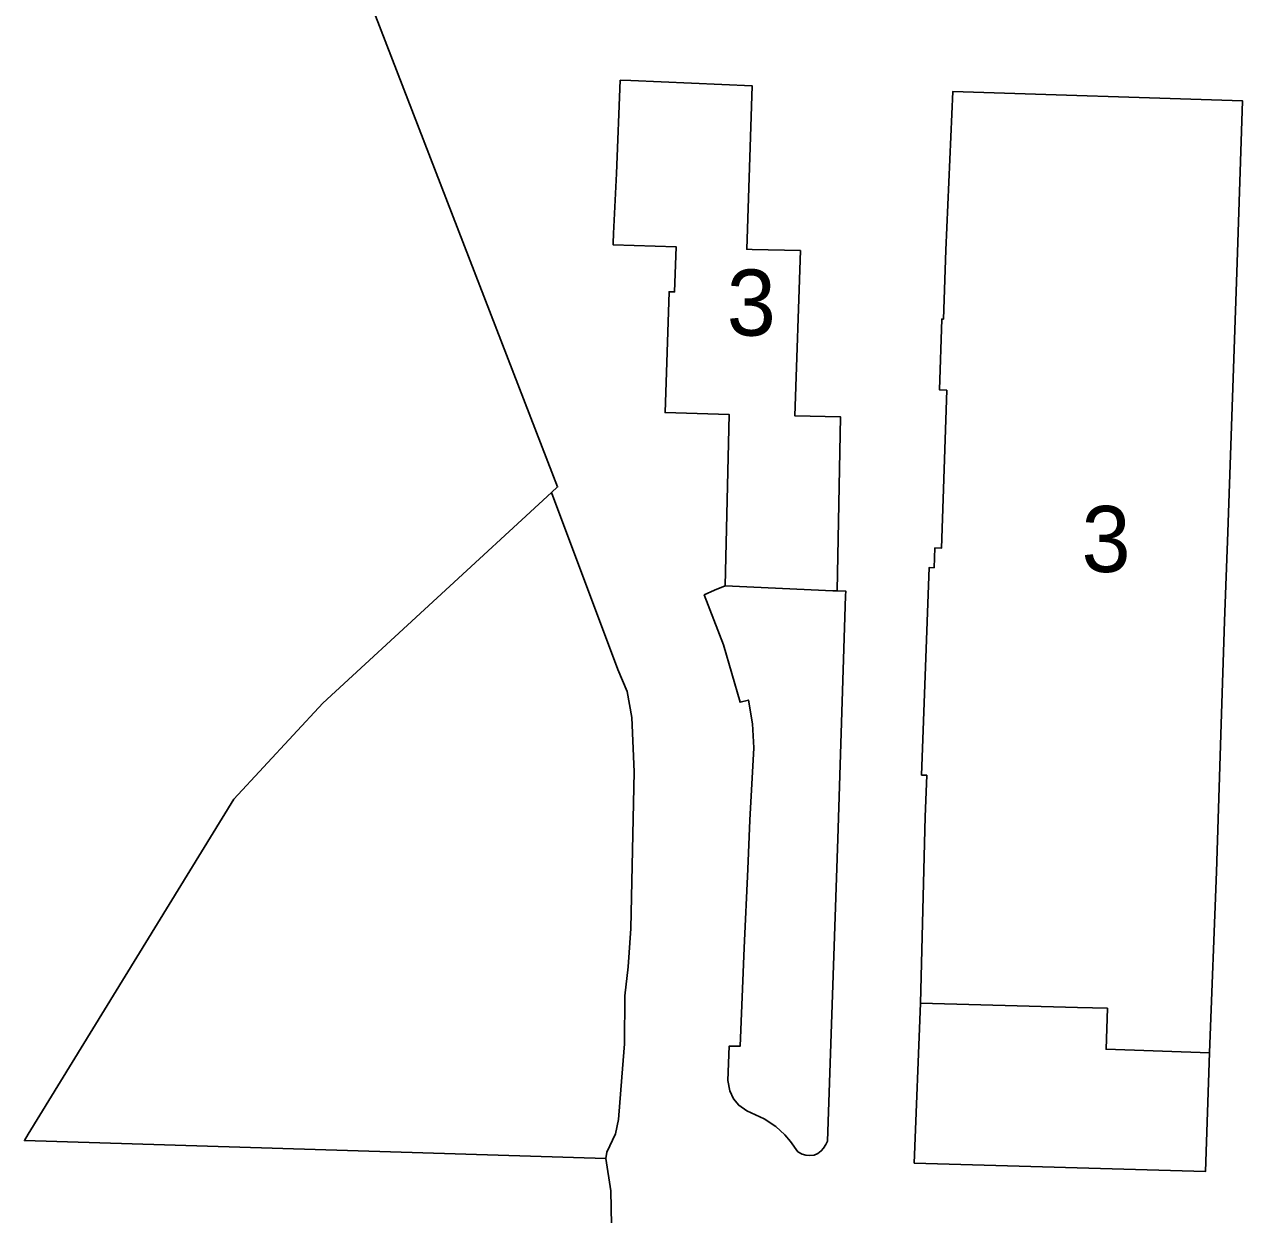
# Model space of a CAD drawing. Extents: x 598968 to 613553, y 4409678 to 4430833.
# Drawn here: x 607300.1 to 607521.4, y 4415642.7 to 4415858.9 of the extents above; entities that cross this region are included whole.
import ezdxf

# ---------------------------------------------------------------- set-up
doc = ezdxf.new("R2010")
doc.units = 0
doc.layers.add('1', color=7, linetype='Continuous')
doc.layers.add("ZONA 3. ILLES  D'EDIFICIS ENTRE MITGERES. EIXAMPLE.", color=7, linetype='Continuous')

msp = doc.modelspace()

# ---------------------------------------------------------------- linework, layer by layer
at = {"layer": '1'}
for points in [[(607406.8143, 4415637.7598), (607406.6242, 4415647.0096), (607405.7007, 4415652.8821), (607300.0976, 4415656.139), (607300.8174, 4415657.3116), (607338.1666, 4415718.1558), (607354.297, 4415735.5965), (607395.8401, 4415773.8555), (607396.9598, 4415774.8866), (607328.465, 4415952.2302)], [(607328.465, 4415952.2302), (607396.9598, 4415774.8866), (607395.8401, 4415773.8555), (607407.8823, 4415741.7238), (607409.6023, 4415737.7039), (607410.4424, 4415733.004), (607410.9024, 4415723.1242), (607410.2425, 4415694.6645), (607409.8025, 4415687.6845), (607409.2025, 4415682.4346), (607409.1176, 4415673.7297), (607408.6326, 4415667.6848), (607408.0326, 4415659.9648), (607407.4927, 4415657.3648), (607405.9392, 4415654.0676), (607405.7007, 4415652.8821), (607406.6242, 4415647.0096), (607406.8143, 4415637.7598)]]:
    msp.add_lwpolyline(points, dxfattribs=at)
for points in [[(607447.7421, 4415755.99), (607449.3024, 4415755.9611), (607449.2618, 4415755.0744), (607447.8579, 4415710.9642), (607445.9849, 4415656.0099), (607445.7069, 4415655.4515), (607445.2822, 4415654.7456), (607444.8522, 4415654.2656), (607444.2208, 4415653.7724), (607443.5495, 4415653.5165), (607442.7978, 4415653.4221), (607442.0503, 4415653.4934), (607441.3723, 4415653.7055), (607440.6261, 4415654.1081), (607439.2823, 4415655.9954), (607438.2623, 4415657.2054), (607436.6323, 4415658.6954), (607434.5023, 4415660.1053), (607431.3374, 4415661.5652), (607429.8624, 4415662.5503), (607428.8924, 4415663.7452), (607428.2324, 4415665.1651), (607427.8724, 4415667.0651), (607428.1224, 4415673.275), (607430.1355, 4415673.3169), (607430.879, 4415691.1786), (607431.5207, 4415705.442), (607431.9172, 4415714.3246), (607432.6221, 4415727.4745), (607432.3521, 4415731.8504), (607431.6268, 4415736.1744), (607430.1121, 4415735.7844), (607427.0821, 4415746.1941), (607423.6121, 4415755.254), (607425.4621, 4415756.134), (607427.3921, 4415756.914), (607427.4073, 4415756.9133), (607428.103, 4415788.0669), (607416.4766, 4415788.3969), (607417.212, 4415810.3432), (607418.212, 4415810.3032), (607418.532, 4415818.4831), (607407.0421, 4415818.8829), (607407.0542, 4415819.1429), (607407.1221, 4415820.9029), (607407.642, 4415831.8128), (607408.342, 4415848.7526), (607410.2619, 4415848.7026), (607432.2817, 4415847.773), (607431.341, 4415818.0563), (607432.3018, 4415818.0234), (607441.0867, 4415817.8285), (607440.0918, 4415787.7839), (607448.3417, 4415787.624)], [(607520.4409, 4415815.675), (607518.7296, 4415766.6552), (607518.1311, 4415750.4957), (607517.5212, 4415731.796), (607516.6613, 4415704.9363), (607515.3915, 4415672.1366), (607515.3907, 4415672.1133), (607514.6715, 4415650.5469), (607461.7621, 4415652.0659), (607462.862, 4415681.1156), (607463.7319, 4415714.9752), (607464.0219, 4415722.4951), (607463.0819, 4415722.5351), (607464.4517, 4415760.2346), (607465.3686, 4415760.1957), (607465.5217, 4415763.7946), (607466.6805, 4415763.755), (607467.6617, 4415792.4592), (607466.3616, 4415792.4943), (607466.7515, 4415805.3842), (607467.0498, 4415805.3739), (607467.4815, 4415817.894), (607468.7914, 4415846.7437), (607521.4108, 4415845.0147)], [(607405.7007, 4415652.8821), (607405.9392, 4415654.0676), (607407.4927, 4415657.3648), (607408.0326, 4415659.9648), (607408.6326, 4415667.6848), (607409.1176, 4415673.7297), (607409.2025, 4415682.4346), (607409.8025, 4415687.6845), (607410.2425, 4415694.6645), (607410.9024, 4415723.1242), (607410.4424, 4415733.004), (607409.6023, 4415737.7039), (607407.8823, 4415741.7238), (607395.8401, 4415773.8555), (607354.297, 4415735.5965), (607338.1666, 4415718.1558), (607300.8174, 4415657.3116), (607300.0976, 4415656.139)], [(607427.4073, 4415756.9133), (607427.3921, 4415756.914), (607425.4621, 4415756.134), (607423.6121, 4415755.254), (607427.0821, 4415746.1941), (607430.1121, 4415735.7844), (607431.6268, 4415736.1744), (607432.3521, 4415731.8504), (607432.6221, 4415727.4745), (607431.9172, 4415714.3246), (607431.5207, 4415705.442), (607430.879, 4415691.1786), (607430.1355, 4415673.3169), (607428.1224, 4415673.275), (607427.8724, 4415667.0651), (607428.2324, 4415665.1651), (607428.8924, 4415663.7452), (607429.8624, 4415662.5503), (607431.3374, 4415661.5652), (607434.5023, 4415660.1053), (607436.6323, 4415658.6954), (607438.2623, 4415657.2054), (607439.2823, 4415655.9954), (607440.6261, 4415654.1081), (607441.3723, 4415653.7055), (607442.0503, 4415653.4934), (607442.7978, 4415653.4221), (607443.5495, 4415653.5165), (607444.2208, 4415653.7724), (607444.8522, 4415654.2656), (607445.2822, 4415654.7456), (607445.7069, 4415655.4515), (607445.9849, 4415656.0099), (607447.8579, 4415710.9642), (607449.2618, 4415755.0744), (607449.3024, 4415755.9611), (607447.7421, 4415755.99), (607446.9668, 4415756.0044)], [(607515.3907, 4415672.1133), (607496.6016, 4415672.7463), (607496.8416, 4415680.1762), (607491.3966, 4415680.3267), (607462.862, 4415681.1156), (607461.7621, 4415652.0659), (607514.6715, 4415650.5469)]]:
    msp.add_lwpolyline(points, close=True, dxfattribs=at)
at = {"layer": "ZONA 3. ILLES  D'EDIFICIS ENTRE MITGERES. EIXAMPLE."}
for points in [[(607447.7421, 4415755.99), (607448.3417, 4415787.624), (607440.0918, 4415787.7839), (607441.0867, 4415817.8285), (607432.3018, 4415818.0234), (607431.341, 4415818.0563), (607432.2817, 4415847.773), (607410.2619, 4415848.7026), (607408.342, 4415848.7526), (607407.642, 4415831.8128), (607407.1221, 4415820.9029), (607407.0542, 4415819.1429), (607407.0421, 4415818.8829), (607418.532, 4415818.4831), (607418.212, 4415810.3032), (607417.212, 4415810.3432), (607416.4766, 4415788.3969), (607428.103, 4415788.0669), (607427.4073, 4415756.9133), (607446.9668, 4415756.0044)], [(607515.3907, 4415672.1133), (607515.3915, 4415672.1366), (607516.6613, 4415704.9363), (607517.5212, 4415731.796), (607518.1311, 4415750.4957), (607518.7296, 4415766.6552), (607520.4409, 4415815.675), (607521.4108, 4415845.0147), (607468.7914, 4415846.7437), (607467.4815, 4415817.894), (607467.0498, 4415805.3739), (607466.7515, 4415805.3842), (607466.3616, 4415792.4943), (607467.6617, 4415792.4592), (607466.6805, 4415763.755), (607465.5217, 4415763.7946), (607465.3686, 4415760.1957), (607464.4517, 4415760.2346), (607463.0819, 4415722.5351), (607464.0219, 4415722.4951), (607463.7319, 4415714.9752), (607462.862, 4415681.1156), (607491.3966, 4415680.3267), (607496.8416, 4415680.1762), (607496.6016, 4415672.7463)]]:
    msp.add_lwpolyline(points, close=True, dxfattribs=at)

# ---------------------------------------------------------------- texts
for p in [(607427.6919, 4415802.3713), (607492.1364, 4415759.4285)]:
    msp.add_text('3', height=12, dxfattribs=at).set_placement(p)

doc.saveas('drawing.dxf')
